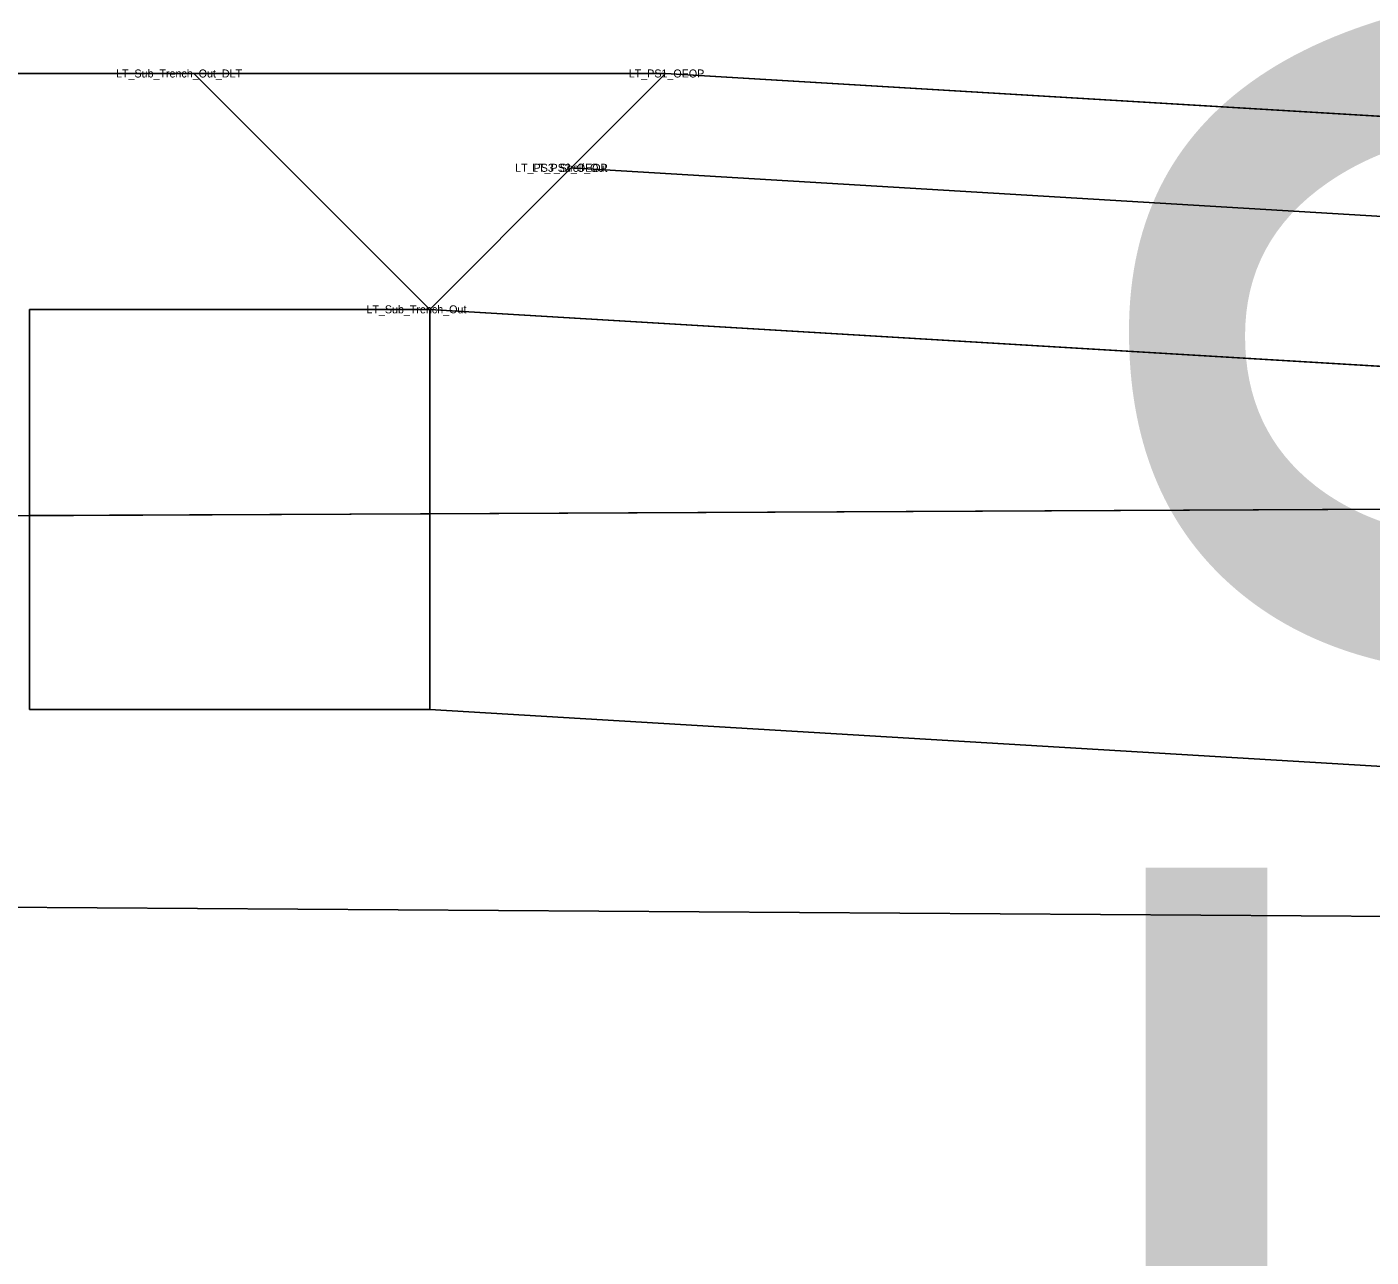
# Model space of a CAD drawing. Extents: x -516 to 303, y -10 to 5017.
# Drawn here: x 144.404 to 147.763, y 3002.875 to 3005.951 of the extents above; entities that cross this region are included whole.
import ezdxf

# ---------------------------------------------------------------- set-up
doc = ezdxf.new("R2010")
doc.units = 0
for name, color, linetype in [('Exist Cross Section Cell', 7, 'Continuous'), ('Exist XS Ground Line', 7, 'Continuous'), ('Prop CMT Pvmt Surface Shoulder', 7, 'Continuous'), ('Prop CMT Shld Paved Course 1', 7, 'Continuous'), ('Prop CMT Shld Paved Course 2', 7, 'Continuous'), ('Prop CMT Shld Paved Course 3', 7, 'Continuous'), ('Prop CMT Slope Grass', 7, 'Continuous'), ('Prop CMT Subgrade Earthwork', 7, 'Continuous'), ('Prop Road Sect_ Material - Contact (General - Major)', 7, 'Continuous'), ('Prop Road Sect_ Misc - Drafting Aid (solid line)', 7, 'Continuous'), ('Prop Road Sect_ Recs - UC Shallow (Outline)', 7, 'Continuous'), ('Prop Road Sect_ Recs - UC Shallow (Pattern)', 7, 'Continuous'), ('Scratch_Level_0', 7, 'Continuous')]:
    doc.layers.add(name, color=color, linetype=linetype)

msp = doc.modelspace()

# ---------------------------------------------------------------- linework, layer by layer
at = {"layer": 'Exist XS Ground Line'}
msp.add_lwpolyline([(127.6717, 3004.8956), (129.9724, 3004.8801), (136.1955, 3004.6894), (149.2025, 3004.7517), (149.5824, 3004.7536), (150.2842, 3004.7329), (152.2526, 3004.7198), (152.8486, 3004.7093), (154.5021, 3004.7218), (155.1545, 3004.7264), (155.8812, 3004.7161), (157.8066, 3004.6912), (159.4913, 3004.6732), (160.5369, 3004.6613), (161.7241, 3004.6468), (162.7917, 3004.6337), (163.3101, 3004.6258), (163.611, 3004.6229), (164.8225, 3004.6077), (165.5966, 3004.5986), (166.1809, 3004.5801)], dxfattribs=at)
at = {"layer": 'Prop CMT Pvmt Surface Shoulder'}
msp.add_line((148, 3005.714), (146, 3005.834), dxfattribs=at)
at = {"layer": 'Prop CMT Shld Paved Course 1'}
for points in [[(148, 3005.714), (146, 3005.834), (145.7642, 3005.5982)], [(145.7642, 3005.5982), (148, 3005.464)]]:
    msp.add_lwpolyline(points, dxfattribs=at)
at = {"layer": 'Prop CMT Shld Paved Course 2'}
for points in [[(148, 3005.464), (145.7642, 3005.5982)], [(145.7642, 3005.5982), (145.7642, 3005.5982)], [(145.7642, 3005.5982), (148, 3005.464)]]:
    msp.add_lwpolyline(points, dxfattribs=at)
at = {"layer": 'Prop CMT Shld Paved Course 3'}
for points in [[(145.7642, 3005.5982), (145.4104, 3005.2444)], [(148, 3005.464), (145.7642, 3005.5982)], [(145.7642, 3005.5982), (145.7642, 3005.5982)], [(145.4104, 3005.2444), (148, 3005.089)]]:
    msp.add_lwpolyline(points, dxfattribs=at)
at = {"layer": 'Prop CMT Slope Grass'}
msp.add_line((146, 3005.834), (140, 3005.834), dxfattribs=at)
at = {"layer": 'Prop CMT Subgrade Earthwork'}
for p, q in [((145.4104, 3005.2444), (144.8208, 3005.834)), ((148, 3005.089), (145.4104, 3005.2444))]:
    msp.add_line(p, q, dxfattribs=at)
at = {"layer": 'Prop Road Sect_ Material - Contact (General - Major)'}
msp.add_line((178.8965, 3003.5176), (2.4565, 3004.7053), dxfattribs=at)
at = {"layer": 'Prop Road Sect_ Misc - Drafting Aid (solid line)'}
for p, q in [((145.4104, 3005.2444), (144.4104, 3005.2444)), ((144.4104, 3005.2444), (144.4104, 3004.2444)), ((145.4104, 3005.2444), (145.4104, 3004.2444))]:
    msp.add_line(p, q, dxfattribs=at)
at = {"layer": 'Prop Road Sect_ Recs - UC Shallow (Outline)'}
msp.add_lwpolyline([(165.6772, 3004.596), (165.5966, 3004.5986), (164.8225, 3004.6077), (161.7224, 3004.6479), (160.5369, 3004.6613), (159.4913, 3004.6732), (157.8066, 3004.6912), (155.8812, 3004.7161), (155.1545, 3004.7264), (154.5021, 3004.7218), (152.8486, 3004.7093), (149.9985, 3004.7392), (148, 3004.746), (145.4104, 3004.7336), (144.4104, 3004.7288), (144.4104, 3004.2444), (145.4104, 3004.2444), (148, 3004.089), (162, 3003.249), (164.6649, 3003.0891), (165.6649, 3003.0891), (165.6649, 3004.0891), (165.6772, 3004.596)], dxfattribs=at)
at = {"layer": 'Prop Road Sect_ Recs - UC Shallow (Pattern)'}
msp.add_lwpolyline([(165.6772, 3004.596), (165.5966, 3004.5986), (164.8225, 3004.6077), (161.7224, 3004.6479), (160.5369, 3004.6613), (159.4913, 3004.6732), (157.8066, 3004.6912), (155.8812, 3004.7161), (155.1545, 3004.7264), (154.5021, 3004.7218), (152.8486, 3004.7093), (149.9985, 3004.7392), (148, 3004.746), (145.4104, 3004.7336), (144.4104, 3004.7288), (144.4104, 3004.2444), (145.4104, 3004.2444), (148, 3004.089), (162, 3003.249), (164.6649, 3003.0891), (165.6649, 3003.0891), (165.6649, 3004.0891), (165.6772, 3004.596)], dxfattribs=at)

# ---------------------------------------------------------------- texts
at = {"layer": 'Exist Cross Section Cell'}
msp.add_text('N 511459.1582', height=2.8, rotation=90, dxfattribs=at).set_placement((150, 2990))
at = {"layer": 'Scratch_Level_0'}
for s, p in [('LT_Sub_Trench_Out_DLT', (144.6264, 3005.824)), ('LT_PS1_OEOP', (145.908, 3005.824)), ('LT_PS3_Shelf_Out', (145.624, 3005.5882)), ('LT_PS3_OEOP', (145.6665, 3005.5882)), ('LT_PS2_OEOP', (145.6665, 3005.5882)), ('LT_Sub_Trench_Out', (145.2524, 3005.2344))]:
    msp.add_text(s, height=0.02, dxfattribs=at).set_placement(p)

doc.saveas('drawing.dxf')
